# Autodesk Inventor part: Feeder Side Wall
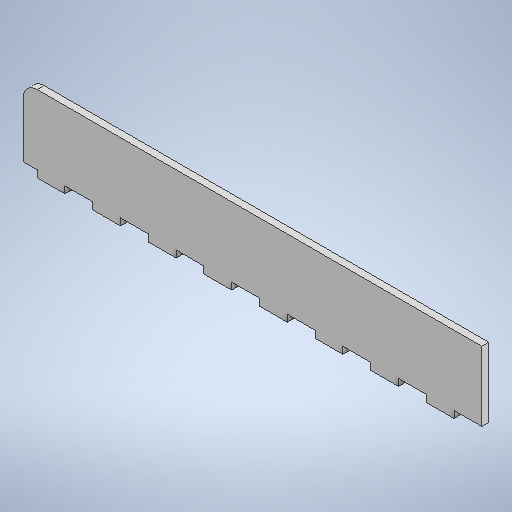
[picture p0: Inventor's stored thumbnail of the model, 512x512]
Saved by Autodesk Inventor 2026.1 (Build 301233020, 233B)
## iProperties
Created: 2026-11
Part Number: Feeder Side Wall
Material: Generic
Document SubType Name: Modeling
Designer: hp
Density: 1 g/cm^3
Appearance: Default
Author: hp
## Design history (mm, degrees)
sketch "Sketch1"
  geometry: L1 (0, 0)-(330, 0); L2 (330, 0)-(330, 50); L3 (330, 50)-(0, 50); L4 (0, 50)-(0, 0); L5 (0, 0)-(330, 0); L6 (330, 0)-(330, -5); L7 (330, -5)-(0, -5); L8 (0, -5)-(0, 0); 1 further point
  constraints: 16 end point, 4 parallel, 2 horizontal, 2 perpendicular
  dimensions: "d0" = 330 distance of L3.end L2.end; "d1" = 50 distance of L2.end L1.end; "d40" = 5 distance of L5.end L6.end; "d50" = 330 distance of L6.end L7.end (= d0)
extrude "Extrusion1" new body sketch "Sketch1" distance "d2" = 5; taper "d3" = 0 deg
fillet "Fillet2" dims "d33" = 10
sketch "Sketch7"
  geometry: L1 (0, -5)-(330, -5) reference; L2 (0, 0)-(330, 0) reference; L3 (330, 0)-(330, -5) reference; L4 (0, -5)-(0, 0) reference; L5 (10, 0)-(30, 0); L6 (30, 0)-(30, -5); L7 (30, -5)-(10, -5); L8 (10, -5)-(10, 0); L9 (50, 0)-(70, 0); L10 (70, 0)-(70, -5); L11 (70, -5)-(50, -5); L12 (50, -5)-(50, 0); L13 (90, 0)-(110, 0); L14 (110, 0)-(110, -5); L15 (110, -5)-(90, -5); L16 (90, -5)-(90, 0); L17 (130, 0)-(150, 0); L18 (150, 0)-(150, -5); L19 (150, -5)-(130, -5); L20 (130, -5)-(130, 0); L21 (170, 0)-(190, 0); L22 (190, 0)-(190, -5); L23 (190, -5)-(170, -5); L24 (170, -5)-(170, 0); L25 (210, 0)-(230, 0); L26 (230, 0)-(230, -5); L27 (230, -5)-(210, -5); L28 (210, -5)-(210, 0); L29 (250, 0)-(270, 0); L30 (270, 0)-(270, -5); L31 (270, -5)-(250, -5); L32 (250, -5)-(250, 0); L33 (290, 0)-(310, 0); L34 (310, 0)-(310, -5); L35 (310, -5)-(290, -5); L36 (290, -5)-(290, 0); 4 further points
  constraints: 64 end point, 2 horizontal, 2 parallel, 1 perpendicular, 1 point on line, 57 other
  dimensions: "d51" = 20 distance of L6.end L7.end; "d52" = 10 distance between parallel lines of L4 L8; "d66" = 40 distance of L5.start L9.start
extrude "Extrusion3" join sketch "Sketch7" distance "d62" = 5; taper "d63" = 0 deg
body "Solid1"
node "Sketch Rectangular Pattern3" dims "d66" = 40, "d69" = 10
